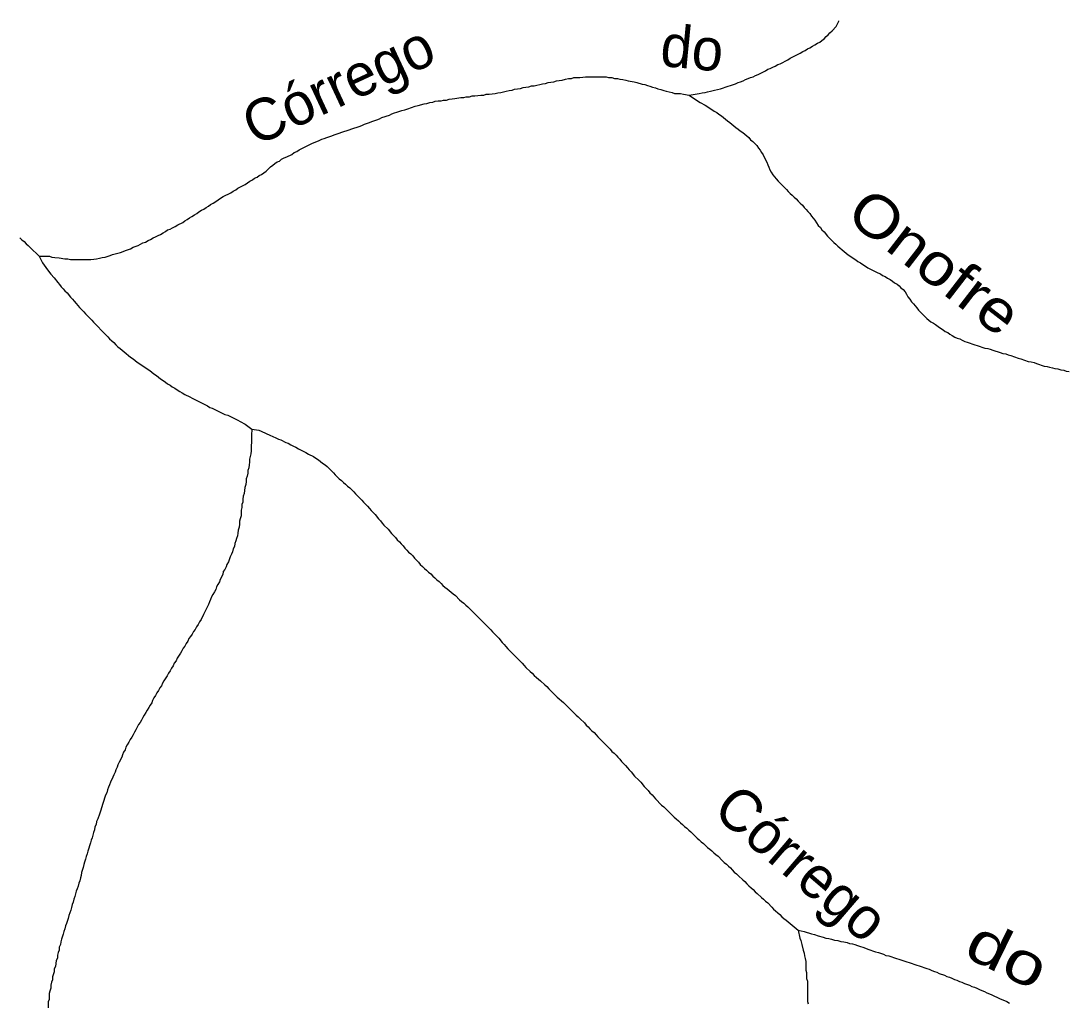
# Model space of a CAD drawing. Extents: x 652.3 to 678, y 7316.9 to 7344.9.
# Drawn here: x 672.065 to 674.062, y 7332.83 to 7334.702 of the extents above; entities that cross this region are included whole.
import ezdxf
from ezdxf.enums import TextEntityAlignment as Align

# ---------------------------------------------------------------- set-up
doc = ezdxf.new("R2010")
doc.units = 0
doc.header["$LTSCALE"] = 0.032
doc.layers.add('61', color=7, linetype='Continuous')
doc.layers.add('7', color=7, linetype='Continuous', lineweight=25)

msp = doc.modelspace()

# ---------------------------------------------------------------- linework, layer by layer
at = {"layer": '7'}
for points in [[(673.3381, 7334.5606), (673.3572, 7334.5638), (673.3628, 7334.5646), (673.3683, 7334.5654), (673.3731, 7334.567), (673.3787, 7334.5678), (673.3866, 7334.5701), (673.3978, 7334.5725), (673.4121, 7334.5773), (673.4169, 7334.5789), (673.4264, 7334.5821), (673.4312, 7334.5845), (673.436, 7334.5861), (673.4408, 7334.5876), (673.4455, 7334.59), (673.4503, 7334.5924), (673.4551, 7334.594), (673.4598, 7334.5956), (673.4646, 7334.598), (673.4694, 7334.5996), (673.4837, 7334.6067), (673.4877, 7334.6099), (673.4925, 7334.6115), (673.4972, 7334.6139), (673.502, 7334.6155), (673.5068, 7334.6187), (673.5116, 7334.6203), (673.5259, 7334.6274), (673.5307, 7334.6306), (673.5498, 7334.6402), (673.5545, 7334.6433), (673.5593, 7334.6457), (673.5633, 7334.6489), (673.5681, 7334.6505), (673.5728, 7334.6537), (673.5776, 7334.6561), (673.5824, 7334.6593), (673.5872, 7334.6616), (673.5911, 7334.6648), (673.5951, 7334.668), (673.5991, 7334.672), (673.6031, 7334.6752), (673.6063, 7334.6792), (673.6102, 7334.6831), (673.6182, 7334.6911), (673.623, 7334.7014), (673.6231, 7334.7018)], [(672.6952, 7334.4961), (672.7095, 7334.5009), (672.7143, 7334.5025), (672.7191, 7334.5049), (672.7286, 7334.5081), (672.7334, 7334.5105), (672.7429, 7334.5136), (672.7477, 7334.5152), (672.7525, 7334.5176), (672.7668, 7334.5224), (672.7716, 7334.5248), (672.7764, 7334.5264), (672.7811, 7334.528), (672.7907, 7334.5312), (672.7962, 7334.5327), (672.8018, 7334.5343), (672.8161, 7334.5391), (672.8217, 7334.5407), (672.8328, 7334.5439), (672.8384, 7334.5447), (672.844, 7334.5463), (672.8496, 7334.5471), (672.8543, 7334.5487), (672.8599, 7334.5495), (672.8655, 7334.5495), (672.8702, 7334.551), (672.8758, 7334.551), (672.8806, 7334.5526), (672.8862, 7334.5534), (672.8917, 7334.5542), (672.9029, 7334.5558), (672.9084, 7334.5558), (672.9132, 7334.5574), (672.9196, 7334.5574), (672.9244, 7334.559), (672.9299, 7334.559), (672.9355, 7334.5598), (672.9411, 7334.5606), (672.9466, 7334.5606), (672.9514, 7334.5622), (672.957, 7334.5622), (672.9625, 7334.563), (672.9681, 7334.5638), (672.9737, 7334.5646), (672.9793, 7334.5654), (672.984, 7334.567), (672.9896, 7334.5678), (672.9952, 7334.5693), (673.0007, 7334.5701), (673.0055, 7334.5717), (673.0111, 7334.5725), (673.0167, 7334.5733), (673.0214, 7334.5749), (673.027, 7334.5757), (673.0326, 7334.5765), (673.0373, 7334.5781), (673.0429, 7334.5781), (673.0477, 7334.5797), (673.0533, 7334.5805), (673.0588, 7334.5821), (673.0644, 7334.5829), (673.0692, 7334.5845), (673.0747, 7334.5853), (673.0803, 7334.5861), (673.0851, 7334.5876), (673.0906, 7334.5884), (673.0962, 7334.5892), (673.1026, 7334.5908), (673.1082, 7334.5924), (673.1137, 7334.5924), (673.1185, 7334.594), (673.1296, 7334.594), (673.1352, 7334.5948), (673.1408, 7334.5956), (673.1798, 7334.5956), (673.1845, 7334.594), (673.1909, 7334.594), (673.1957, 7334.5924), (673.2013, 7334.5924), (673.206, 7334.5908), (673.2116, 7334.59), (673.2172, 7334.5892), (673.2219, 7334.5876), (673.2331, 7334.5861), (673.2386, 7334.5845), (673.2482, 7334.5813), (673.2538, 7334.5805), (673.2585, 7334.5789), (673.2633, 7334.5773), (673.2681, 7334.5757), (673.2737, 7334.5741), (673.2784, 7334.5725), (673.284, 7334.5709), (673.2896, 7334.5693), (673.2943, 7334.5678), (673.2999, 7334.567), (673.3055, 7334.5654), (673.3103, 7334.5638), (673.3214, 7334.5638), (673.327, 7334.5622), (673.3381, 7334.5606)], [(673.3381, 7334.5606), (673.354, 7334.5495), (673.3588, 7334.5463), (673.3683, 7334.5415), (673.3755, 7334.5367), (673.3859, 7334.5296), (673.3906, 7334.5272), (673.3946, 7334.524), (673.3994, 7334.5208), (673.4034, 7334.5176), (673.4073, 7334.5144), (673.4113, 7334.5113), (673.4153, 7334.5081), (673.4193, 7334.5049), (673.4232, 7334.5017), (673.4272, 7334.4985), (673.4312, 7334.4953), (673.4352, 7334.4922), (673.44, 7334.489), (673.4439, 7334.4858), (673.4479, 7334.4826), (673.4519, 7334.4794), (673.4551, 7334.4755), (673.4591, 7334.4723), (673.467, 7334.4643), (673.4702, 7334.4595), (673.4734, 7334.4556), (673.4758, 7334.4508), (673.4789, 7334.4468), (673.4837, 7334.4373), (673.4861, 7334.4325), (673.4877, 7334.4277), (673.4901, 7334.4229), (673.4917, 7334.4182), (673.4941, 7334.4134), (673.4972, 7334.4086), (673.5036, 7334.4007), (673.5076, 7334.3967), (673.5116, 7334.3927), (673.5195, 7334.3847), (673.5235, 7334.3808), (673.5267, 7334.3768), (673.5307, 7334.3728), (673.5346, 7334.3696), (673.5378, 7334.3657), (673.5418, 7334.3625), (673.5458, 7334.3585), (673.5498, 7334.3545), (673.5537, 7334.3505), (673.5569, 7334.3466), (673.5609, 7334.3426), (673.5641, 7334.3386), (673.5681, 7334.3346), (673.5712, 7334.3298), (673.5776, 7334.3219), (673.584, 7334.3123), (673.588, 7334.3084), (673.5911, 7334.3036), (673.5951, 7334.2996), (673.6015, 7334.2917), (673.6134, 7334.2797), (673.6174, 7334.2765), (673.6214, 7334.2726), (673.6254, 7334.2694), (673.6293, 7334.2654), (673.6333, 7334.2622), (673.6373, 7334.259), (673.6413, 7334.2558)], [(672.0992, 7334.2535), (672.1191, 7334.2535), (672.1239, 7334.2519), (672.1295, 7334.2511), (672.1374, 7334.2503), (672.1486, 7334.2487), (672.1541, 7334.2487), (672.1589, 7334.2471), (672.1979, 7334.2471), (672.2035, 7334.2479), (672.209, 7334.2487), (672.2146, 7334.2495), (672.2194, 7334.2511), (672.2249, 7334.2519), (672.2345, 7334.2551), (672.2393, 7334.2566), (672.244, 7334.2582), (672.2496, 7334.259), (672.2544, 7334.2606), (672.2592, 7334.2622), (672.2639, 7334.2646), (672.2735, 7334.2678), (672.2783, 7334.271), (672.2878, 7334.2741), (672.2973, 7334.2789), (672.3021, 7334.2805), (672.3069, 7334.2837), (672.3117, 7334.2853), (672.3164, 7334.2885), (672.3212, 7334.2901), (672.326, 7334.2932), (672.3308, 7334.2948), (672.3355, 7334.298), (672.3403, 7334.3004), (672.3443, 7334.3036), (672.3491, 7334.3052), (672.3538, 7334.3076), (672.3586, 7334.31), (672.3634, 7334.3131), (672.3729, 7334.3179), (672.3769, 7334.3211), (672.3817, 7334.3235), (672.3857, 7334.3267), (672.3904, 7334.329), (672.3952, 7334.3322), (672.4, 7334.3346), (672.404, 7334.3378), (672.4087, 7334.341), (672.4135, 7334.3434), (672.4175, 7334.3466), (672.4223, 7334.3489), (672.4262, 7334.3521), (672.431, 7334.3545), (672.4358, 7334.3577), (672.4406, 7334.3609), (672.4453, 7334.3641), (672.4501, 7334.3672), (672.4644, 7334.3744), (672.4692, 7334.3776), (672.474, 7334.38), (672.478, 7334.3832), (672.4923, 7334.3903), (672.4963, 7334.3935), (672.501, 7334.3967), (672.5058, 7334.3991), (672.5098, 7334.4023), (672.5146, 7334.4038), (672.5185, 7334.407), (672.5233, 7334.4094), (672.5273, 7334.4126), (672.5321, 7334.4158), (672.54, 7334.4237), (672.5448, 7334.4269), (672.5488, 7334.4301), (672.5528, 7334.4333), (672.5575, 7334.4349), (672.5615, 7334.4381), (672.5663, 7334.4412), (672.5711, 7334.4428), (672.5806, 7334.4476), (672.5854, 7334.4508), (672.5902, 7334.4532), (672.5949, 7334.4564), (672.6188, 7334.4683), (672.6236, 7334.4699), (672.6284, 7334.4723), (672.6331, 7334.4739), (672.6379, 7334.4763), (672.6427, 7334.4778), (672.6475, 7334.4794), (672.657, 7334.4826), (672.6618, 7334.485), (672.6713, 7334.4882), (672.6761, 7334.4898), (672.6904, 7334.4946), (672.6952, 7334.4961)], [(672.0626, 7334.2885), (672.0666, 7334.2845), (672.0706, 7334.2813), (672.0746, 7334.2773), (672.0785, 7334.2741), (672.0825, 7334.2702), (672.0992, 7334.2535)], [(672.0992, 7334.2535), (672.1056, 7334.2407), (672.1088, 7334.2367), (672.1151, 7334.2272), (672.1215, 7334.2192), (672.1279, 7334.2121), (672.135, 7334.2033), (672.1382, 7334.1994), (672.1414, 7334.1954), (672.1454, 7334.1914), (672.1486, 7334.1874), (672.1525, 7334.1834), (672.1589, 7334.1755), (672.1629, 7334.1715), (672.1661, 7334.1675), (672.17, 7334.1635), (672.1764, 7334.1556), (672.1844, 7334.1476), (672.1875, 7334.1437), (672.1955, 7334.1357), (672.1995, 7334.1317), (672.2027, 7334.1277), (672.2265, 7334.1039), (672.2305, 7334.0999), (672.2337, 7334.0959), (672.2377, 7334.0919), (672.2417, 7334.0888), (672.2456, 7334.0848), (672.2496, 7334.0808), (672.2536, 7334.0776), (672.2576, 7334.0744), (672.2615, 7334.0712), (672.2655, 7334.0681), (672.2695, 7334.0641), (672.2735, 7334.0609), (672.2783, 7334.0577), (672.2822, 7334.0545), (672.2862, 7334.0514), (672.291, 7334.0482), (672.2958, 7334.045), (672.3005, 7334.0418), (672.3053, 7334.0386), (672.3101, 7334.0354), (672.3141, 7334.0323), (672.318, 7334.0291), (672.3228, 7334.0259), (672.3268, 7334.0227), (672.3308, 7334.0195), (672.3355, 7334.0163), (672.3403, 7334.0132), (672.3443, 7334.01), (672.3491, 7334.0076), (672.353, 7334.0044), (672.3578, 7334.002), (672.3626, 7333.9988), (672.3674, 7333.9957), (672.3721, 7333.9933), (672.3769, 7333.9901), (672.3865, 7333.9853), (672.3912, 7333.9829), (672.4199, 7333.9686), (672.4247, 7333.9654), (672.4294, 7333.9638), (672.4533, 7333.9519), (672.4589, 7333.9503), (672.478, 7333.9408), (672.4827, 7333.9384), (672.4923, 7333.9336), (672.505, 7333.924)], [(673.6413, 7334.2558), (673.646, 7334.2527), (673.6508, 7334.2495), (673.6556, 7334.2463), (673.6596, 7334.2431), (673.6643, 7334.2407), (673.6691, 7334.2375), (673.6739, 7334.2344), (673.6787, 7334.2312), (673.6978, 7334.2216), (673.7025, 7334.22), (673.7065, 7334.2169), (673.7113, 7334.2145), (673.7161, 7334.2113), (673.7208, 7334.2089), (673.7256, 7334.2057), (673.7296, 7334.2025), (673.7344, 7334.2001), (673.7383, 7334.197), (673.7415, 7334.193), (673.7455, 7334.1898), (673.7495, 7334.1858), (673.7519, 7334.1811), (673.755, 7334.1763), (673.7582, 7334.1715), (673.7614, 7334.1667), (673.7654, 7334.1628), (673.7718, 7334.1548), (673.7749, 7334.1508), (673.7909, 7334.1349), (673.7948, 7334.1317), (673.7988, 7334.1285), (673.8036, 7334.1261), (673.8076, 7334.123), (673.8123, 7334.1198), (673.8171, 7334.1166), (673.8219, 7334.1134), (673.8259, 7334.1102), (673.8306, 7334.1078), (673.8346, 7334.1047), (673.8394, 7334.1023), (673.8442, 7334.0991), (673.8489, 7334.0975), (673.8537, 7334.0959), (673.8585, 7334.0935), (673.8633, 7334.0911), (673.868, 7334.0895), (673.8824, 7334.0848), (673.8871, 7334.0832), (673.9015, 7334.0784), (673.907, 7334.0776), (673.9118, 7334.076), (673.9166, 7334.0744), (673.9309, 7334.0697), (673.9357, 7334.0681), (673.9412, 7334.0673), (673.946, 7334.0657), (673.9508, 7334.0641), (673.9651, 7334.0593), (673.9699, 7334.0577), (673.9842, 7334.0529), (673.9898, 7334.0521), (673.9953, 7334.0506), (674.0001, 7334.049), (674.0144, 7334.0442), (674.02, 7334.0434), (674.0248, 7334.0418), (674.0304, 7334.041), (674.0351, 7334.0394), (674.0407, 7334.0386), (674.0463, 7334.037), (674.0518, 7334.0362), (674.0566, 7334.0346), (674.0622, 7334.0338)], [(672.505, 7333.924), (672.5042, 7333.9121), (672.5042, 7333.9026), (672.5034, 7333.8882), (672.5034, 7333.8827), (672.5026, 7333.8771), (672.5018, 7333.8715)], [(672.505, 7333.924), (672.5178, 7333.9217), (672.5225, 7333.9201), (672.5321, 7333.9153), (672.5392, 7333.9121), (672.5504, 7333.9073), (672.5552, 7333.9049), (672.5599, 7333.9034), (672.5695, 7333.8986), (672.5742, 7333.897), (672.579, 7333.8938), (672.5838, 7333.8914), (672.5886, 7333.8898), (672.5933, 7333.8866), (672.6077, 7333.8795), (672.6124, 7333.8763), (672.622, 7333.8715), (672.6268, 7333.8683), (672.6315, 7333.8652), (672.6355, 7333.862), (672.6395, 7333.8588), (672.6443, 7333.8556), (672.6482, 7333.8524), (672.6602, 7333.8405), (672.6634, 7333.8365), (672.6673, 7333.8333), (672.6713, 7333.8294), (672.6753, 7333.8262), (672.6793, 7333.8222), (672.6833, 7333.819), (672.6872, 7333.815), (672.6912, 7333.8119), (672.6952, 7333.8079), (672.6992, 7333.8047), (672.7024, 7333.8007), (672.7143, 7333.7888), (672.7175, 7333.7848), (672.7254, 7333.7768), (672.7286, 7333.7729), (672.7318, 7333.7689), (672.7398, 7333.7609), (672.7461, 7333.753), (672.7501, 7333.749), (672.7533, 7333.745), (672.7565, 7333.741), (672.7644, 7333.7331), (672.7708, 7333.7251), (672.7787, 7333.7172), (672.7819, 7333.7132), (672.7859, 7333.7092), (672.7891, 7333.7052), (672.7931, 7333.7013), (672.7962, 7333.6973), (672.8002, 7333.6933), (672.8034, 7333.6893), (672.8074, 7333.6861), (672.8114, 7333.6822), (672.8145, 7333.6782), (672.8225, 7333.6702), (672.8257, 7333.6662), (672.8297, 7333.6623), (672.8336, 7333.6583), (672.8376, 7333.6551), (672.8416, 7333.6511), (672.8456, 7333.6479), (672.8496, 7333.644), (672.8535, 7333.6408), (672.8575, 7333.6368), (672.8615, 7333.6336), (672.8655, 7333.6296), (672.8687, 7333.6257), (672.8726, 7333.6225), (672.8766, 7333.6193), (672.8806, 7333.6161), (672.8846, 7333.6129), (672.8885, 7333.6097), (672.8925, 7333.6066), (672.9005, 7333.5986), (672.9045, 7333.5954), (672.9084, 7333.5922), (672.9124, 7333.5883), (672.9164, 7333.5851), (672.9283, 7333.5731), (672.9323, 7333.5692), (672.9602, 7333.5413), (672.9633, 7333.5373), (672.9753, 7333.5254), (672.9816, 7333.5174), (672.9856, 7333.5135), (672.9888, 7333.5095), (672.9928, 7333.5055), (672.996, 7333.5015), (673.0198, 7333.4777), (673.0238, 7333.4737), (673.027, 7333.4697), (673.035, 7333.4617), (673.0389, 7333.4586), (673.0429, 7333.4546), (673.0469, 7333.4506)], [(672.5018, 7333.8715), (672.5002, 7333.8668), (672.5002, 7333.8612), (672.4995, 7333.8556), (672.4987, 7333.85), (672.4971, 7333.8453), (672.4971, 7333.8397), (672.4955, 7333.8341), (672.4939, 7333.8294), (672.4939, 7333.8238), (672.4931, 7333.8182), (672.4915, 7333.8126), (672.4907, 7333.8071), (672.4899, 7333.8015), (672.4883, 7333.7959), (672.4875, 7333.7904), (672.4875, 7333.7848), (672.4859, 7333.78), (672.4859, 7333.7745), (672.4843, 7333.7697), (672.4843, 7333.7585), (672.4827, 7333.753), (672.4812, 7333.7482), (672.4812, 7333.7426), (672.4804, 7333.7371), (672.4788, 7333.7315), (672.478, 7333.7259), (672.4772, 7333.7203), (672.4756, 7333.7156), (672.474, 7333.7108), (672.4724, 7333.706), (672.4716, 7333.7005), (672.4692, 7333.6957), (672.4676, 7333.6901), (672.466, 7333.6853), (672.4636, 7333.6806), (672.4605, 7333.671), (672.4573, 7333.6662), (672.4557, 7333.6615), (672.4533, 7333.6567), (672.4501, 7333.6527), (672.4493, 7333.6471), (672.4446, 7333.6376), (672.443, 7333.6328), (672.4398, 7333.628), (672.4374, 7333.6233), (672.4358, 7333.6185), (672.4334, 7333.6137), (672.4302, 7333.609), (672.4278, 7333.6042), (672.4262, 7333.5994), (672.4239, 7333.5946), (672.4223, 7333.5899), (672.4151, 7333.5755), (672.4127, 7333.5708), (672.4079, 7333.5612), (672.4048, 7333.5564), (672.4024, 7333.5517), (672.3992, 7333.5469), (672.3968, 7333.5421), (672.3936, 7333.5381), (672.3912, 7333.5334), (672.3881, 7333.5286), (672.3849, 7333.5246), (672.3825, 7333.5198), (672.3793, 7333.5151), (672.3769, 7333.5103), (672.3737, 7333.5063), (672.3713, 7333.5015), (672.369, 7333.4968), (672.3626, 7333.4872), (672.3602, 7333.4824), (672.357, 7333.4777), (672.3546, 7333.4729), (672.3515, 7333.4681), (672.3491, 7333.4633), (672.3459, 7333.4586), (672.3435, 7333.4538), (672.3371, 7333.4442), (672.3347, 7333.4395), (672.3324, 7333.4347), (672.3292, 7333.4307), (672.3268, 7333.4259), (672.3236, 7333.4212), (672.3212, 7333.4164), (672.318, 7333.4116), (672.3156, 7333.4068), (672.3141, 7333.4021), (672.3109, 7333.3981), (672.3085, 7333.3933), (672.3053, 7333.3885), (672.3029, 7333.3838), (672.2997, 7333.379), (672.2973, 7333.3742), (672.2942, 7333.3694), (672.2918, 7333.3647), (672.2886, 7333.3607), (672.2862, 7333.3559), (672.2838, 7333.3511), (672.2814, 7333.3464), (672.2783, 7333.3416)], [(673.0469, 7333.4506), (673.0509, 7333.4474), (673.0548, 7333.4442), (673.0628, 7333.4363), (673.0668, 7333.4331), (673.0708, 7333.4291), (673.0867, 7333.4132), (673.0906, 7333.41), (673.0946, 7333.4061), (673.0986, 7333.4029), (673.1066, 7333.3949), (673.1105, 7333.3909), (673.1225, 7333.379), (673.1265, 7333.3758), (673.1304, 7333.3718), (673.1384, 7333.3639), (673.1416, 7333.3599), (673.1456, 7333.3567), (673.1487, 7333.3527), (673.1527, 7333.3488), (673.1567, 7333.3456), (673.1607, 7333.3416), (673.1639, 7333.3376), (673.1678, 7333.3336), (673.1877, 7333.3138), (673.1909, 7333.3098), (673.1949, 7333.3066), (673.1989, 7333.3026), (673.202, 7333.2986), (673.206, 7333.2947), (673.2092, 7333.2907), (673.2132, 7333.2867), (673.2164, 7333.2827), (673.2203, 7333.2787), (673.2235, 7333.2748), (673.2275, 7333.2708), (673.2339, 7333.2628), (673.2418, 7333.2549), (673.2458, 7333.2509), (673.2522, 7333.2429), (673.2601, 7333.235), (673.2633, 7333.231), (673.2673, 7333.227), (673.2705, 7333.223), (673.2737, 7333.2191), (673.2856, 7333.2071), (673.2896, 7333.2039), (673.2936, 7333.2), (673.3095, 7333.1841), (673.3134, 7333.1809), (673.3174, 7333.1777), (673.3214, 7333.1737), (673.3254, 7333.1705), (673.3294, 7333.1665), (673.3333, 7333.1634), (673.3373, 7333.1594), (673.3413, 7333.1562), (673.3532, 7333.1443), (673.3572, 7333.1411), (673.3612, 7333.1371), (673.3652, 7333.1339), (673.3691, 7333.1307), (673.3731, 7333.1268), (673.3771, 7333.1236), (673.3811, 7333.1204), (673.3851, 7333.1164), (673.389, 7333.1132), (673.393, 7333.1101), (673.401, 7333.1021), (673.4049, 7333.0981), (673.4089, 7333.0949), (673.4129, 7333.091), (673.4169, 7333.0878), (673.4201, 7333.0838), (673.424, 7333.0798), (673.428, 7333.0766), (673.432, 7333.0727), (673.44, 7333.0647), (673.4439, 7333.0615), (673.4479, 7333.0575), (673.4519, 7333.0536), (673.4559, 7333.0496), (673.4598, 7333.0464), (673.4638, 7333.0424), (673.4678, 7333.0392), (673.4758, 7333.0313), (673.4797, 7333.0281), (673.4837, 7333.0241), (673.4877, 7333.0209), (673.4957, 7333.013), (673.4988, 7333.009), (673.5028, 7333.0058), (673.5068, 7333.0018), (673.5108, 7332.9987), (673.5148, 7332.9947), (673.5187, 7332.9915), (673.5227, 7332.9883), (673.5267, 7332.9851), (673.5307, 7332.9819), (673.5346, 7332.9788), (673.5458, 7332.9692)], [(672.2783, 7333.3416), (672.2759, 7333.3368), (672.2727, 7333.3321), (672.2703, 7333.3273), (672.2671, 7333.3225), (672.2647, 7333.3177), (672.2631, 7333.313), (672.26, 7333.3082), (672.2584, 7333.3034), (672.2568, 7333.2986), (672.252, 7333.2891), (672.2496, 7333.2843), (672.248, 7333.2795), (672.2456, 7333.2748), (672.244, 7333.27), (672.2417, 7333.2652), (672.2401, 7333.2604), (672.2353, 7333.2509), (672.2337, 7333.2461), (672.2313, 7333.2413), (672.2297, 7333.2366), (672.2281, 7333.231), (672.2257, 7333.2262), (672.2241, 7333.2207), (672.2226, 7333.2159), (672.221, 7333.2103), (672.2162, 7333.196), (672.2146, 7333.1904), (672.2114, 7333.1809), (672.209, 7333.1761), (672.2082, 7333.1705), (672.2058, 7333.1658), (672.205, 7333.1602), (672.2027, 7333.1554), (672.2019, 7333.1498), (672.2003, 7333.1451), (672.1987, 7333.1403), (672.1971, 7333.1355), (672.1955, 7333.1299), (672.1939, 7333.1252), (672.1923, 7333.1196), (672.1907, 7333.1148), (672.1891, 7333.1093), (672.1875, 7333.1045), (672.186, 7333.0989), (672.1844, 7333.0941), (672.1836, 7333.0886), (672.1804, 7333.079), (672.1796, 7333.0735), (672.178, 7333.0687), (672.1772, 7333.0631), (672.1748, 7333.0583), (672.174, 7333.0528), (672.1716, 7333.048), (672.17, 7333.0432), (672.1684, 7333.0384), (672.1677, 7333.0329), (672.1653, 7333.0281), (672.1645, 7333.0225), (672.1621, 7333.0178), (672.1613, 7333.0122), (672.1597, 7333.0074), (672.1581, 7333.0018), (672.1557, 7332.9971), (672.1549, 7332.9915), (672.1517, 7332.9819), (672.1494, 7332.9772), (672.1486, 7332.9716), (672.1462, 7332.9668), (672.1454, 7332.9613), (672.1422, 7332.9517), (672.1406, 7332.9469), (672.1398, 7332.9414), (672.1374, 7332.9366), (672.1374, 7332.931), (672.1358, 7332.9263), (672.1342, 7332.9215), (672.1342, 7332.9159), (672.1318, 7332.9111), (672.131, 7332.9056), (672.1303, 7332.9), (672.1279, 7332.8952), (672.1279, 7332.8896), (672.1247, 7332.8801), (672.1247, 7332.8745), (672.1231, 7332.8698), (672.1215, 7332.8642), (672.1215, 7332.8586), (672.1199, 7332.853), (672.1183, 7332.8483), (672.1183, 7332.8371), (672.1167, 7332.8324), (672.1167, 7332.8212)], [(673.5458, 7332.9692), (673.549, 7332.9541), (673.5506, 7332.9493), (673.5529, 7332.9414), (673.5553, 7332.931), (673.5569, 7332.9255), (673.5577, 7332.9199), (673.5593, 7332.9151), (673.5601, 7332.9095), (673.5601, 7332.8928), (673.5617, 7332.8881), (673.5617, 7332.8769), (673.5633, 7332.8721), (673.5633, 7332.8332), (673.5649, 7332.8284)], [(673.5458, 7332.9692), (673.5569, 7332.9668), (673.5712, 7332.9621), (673.5768, 7332.9605), (673.584, 7332.9581), (673.5935, 7332.9557), (673.5983, 7332.9541), (673.6039, 7332.9533), (673.6094, 7332.9517), (673.615, 7332.9501), (673.6214, 7332.9493), (673.6269, 7332.9477), (673.6325, 7332.9469), (673.6389, 7332.9453), (673.6437, 7332.9438), (673.6492, 7332.943), (673.654, 7332.9414), (673.6588, 7332.9398), (673.6643, 7332.9382), (673.6691, 7332.9366), (673.6739, 7332.935), (673.6787, 7332.9326), (673.693, 7332.9278), (673.6986, 7332.9263), (673.7081, 7332.9231), (673.7129, 7332.9207), (673.7184, 7332.9199), (673.7328, 7332.9151), (673.7375, 7332.9135), (673.7471, 7332.9103), (673.7527, 7332.9087), (673.7574, 7332.9072), (673.7718, 7332.9024), (673.7765, 7332.9008), (673.7909, 7332.896), (673.7956, 7332.8944), (673.8004, 7332.892), (673.8052, 7332.8904), (673.81, 7332.8889), (673.8147, 7332.8865), (673.8243, 7332.8833), (673.829, 7332.8809), (673.8338, 7332.8793), (673.8386, 7332.8777), (673.8434, 7332.8753), (673.8481, 7332.8737), (673.8529, 7332.8713), (673.8577, 7332.8698), (673.8625, 7332.8674), (673.872, 7332.8642), (673.8768, 7332.8618), (673.8816, 7332.8602), (673.8863, 7332.8586), (673.8911, 7332.8562), (673.8959, 7332.8538), (673.9007, 7332.8523), (673.9054, 7332.8499), (673.9102, 7332.8475), (673.915, 7332.8459), (673.9198, 7332.8435), (673.9245, 7332.8411), (673.9293, 7332.8387), (673.9341, 7332.8371), (673.9389, 7332.8347), (673.9436, 7332.8332), (673.9484, 7332.83)]]:
    msp.add_lwpolyline(points, dxfattribs=at)

# ---------------------------------------------------------------- texts
at = {"layer": '61'}
for s, rotation, p in [('do', 354.395, (673.34, 7334.6107)), ('Córrego', 25.015, (672.6862, 7334.5437)), ('Córrego', 319.412, (673.5265, 7333.0668))]:
    msp.add_text(s, height=0.08, rotation=rotation, dxfattribs=at).set_placement(p, align=Align.CENTER)
for s, rotation, width, p in [('Onofre', 322.346, 1.15, (673.782, 7334.2112)), ('do', 333.947, 1.3, (673.9272, 7332.8868))]:
    msp.add_text(s, height=0.08, rotation=rotation, dxfattribs=dict(at, width=width)).set_placement(p, align=Align.CENTER)

doc.saveas('drawing.dxf')
